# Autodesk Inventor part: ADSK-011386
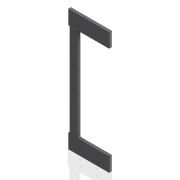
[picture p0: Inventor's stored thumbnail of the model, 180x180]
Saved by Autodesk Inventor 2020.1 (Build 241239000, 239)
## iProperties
Created: 2000-01
Part Number: ADSK-011386
Material: Acier doux
Document SubType Name: Modeling
Designer: glanglot
Density: 7.86 g/cm^3
Appearance: Metal-Steel(Polish)
Mass: 573.757 g
Surface Area: 299.43 cm^2
Volume: 72.997 cm^3
Control State: 0
Master: False
Checked Out: False
Shininess: 0.0
Length Units: 11269
Angle Units: 11279
Time Units: 11290
Mass Units: 11283
Length Display Precision: 5
Angle Display Precision: 5
Compacted: True
Cutlength: 11.97
Material Desc: FLAT,HRS,0.250X04.000
Material_Number: A084338
Dimensions: 102x304x6,4 mm
Mass: 0,574 kg
Density: 0.0
Volumn: 0.0
Area: 0.0
PropertySet Name: Model Information
Author: glanglot
Revision Number: -
Title: ADSK-011386
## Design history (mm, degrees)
node "Extrusion1" dims "d12" = 6.35, "d13" = 0
  sketch "Sketch1"
    geometry: L1 (102, 35)-(0, 35); L2 (0, 35)-(0, 0); L3 (0, 0)-(102, 0); L4 (102, 0)-(102, 35); 1 further point
    constraints: 8 end point, 2 parallel, 1 coincident, 1 horizontal, 1 perpendicular
    dimensions: "d0" = 102 distance of L1.start L1.end; "d1" = 35 distance of L1.end L2.end
node "Hole1" dims "d22" = 3.242, "d23" = 14.2875, "d24" = 6.35, "d25" = 60 deg, "d26" = 3.175, "d27" = 118 deg, "d55" = 8
  sketch "Sketch2"
    geometry: L1 (102, 35)-(102, 0) reference; L2 (30.5, 27.5)-(71.5, 27.5); L3 (71.5, 27.5)-(71.5, 12.5); L4 (71.5, 12.5)-(30.5, 12.5); L5 (30.5, 12.5)-(30.5, 27.5); L6 (0, 35)-(102, 35) reference; 2 further points
    constraints: 8 end point, 2 coincident, 2 parallel, 1 horizontal, 1 perpendicular
    dimensions: "d51" = 41 distance of L2.start L2.end; "d52" = 15 distance of L2.end L3.end; "d53" = 30.5 distance between parallel lines of L1 L3; "d54" = 7.5 distance between parallel lines of L6 L2
node "Extrusion2" dims "d33" = 6.35 (= d12), "d34" = 0
  sketch "Sketch3"
    geometry: L1 (102, 35)-(102, 0) reference; L2 (102, 0)-(0, 0) reference; L3 (23, 0)-(23, -117); L4 (23, -117)-(4, -117); L5 (4, -117)-(4, 0)
    constraints: 6 end point, 3 perpendicular, 2 point on line
    dimensions: "d30" = 79 distance between parallel lines of L3 L1; "d36" = 117 distance between parallel lines of L2 L4; "d48" = 19 distance between parallel lines of L5 L3
workplane "Work Plane1"
node "Hole2" dims "d41" = 3.242, "d42" = 9.525, "d43" = 6.35, "d44" = 60 deg, "d45" = 19.05, "d46" = 118 deg, "d56" = 8
  sketch "Sketch4"
    geometry: L1 (4, -117)-(23, -117) reference; L2 (13.5, -79.5)-(13.5, -104.5); 1 further point
    constraints: 2 end point, 1 midpoint, 1 vertical, 1 vertical alignment
    dimensions: "d37" = 12.5 distance from line of L2.end L1; "d57" = 25 distance of L2.end L2.start
node "Fillet1" dims "d47" = 3.175
node "Mirror1"
node "Solide1"
node "Corps solides"
node "Corps surfaciques"
